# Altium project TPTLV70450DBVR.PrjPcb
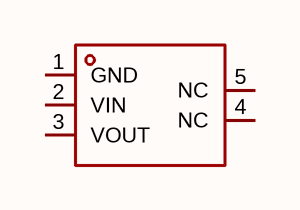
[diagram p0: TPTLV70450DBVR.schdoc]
1 sheet, 1 parts. Net scope: global (net labels, ports and power ports of the same name join across sheets).

## Sheet TPTLV70450DBVR.schdoc
size 127 x 101 mm

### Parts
U?  tptlv70450dbvr  [SOT-23-5_L3.0-W1.6-P0.95-LS2.8-BR]  (value not drawn)

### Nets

Not connected (* = marked no-connect by the designer): U? 1(GND) 2(VIN) 3(VOUT) 4(NC) 5(NC)

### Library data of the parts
U? = tptlv70450dbvr: 输出极性:正极;工作电压:36V;输出电压:5V;输出电流:150mA;电源纹波抑制比(PSRR):68dB;输出类型:固定;; Manufacturer: TECH PUBLIC(台舟); AddInBom: yes; ModelId: 72410e292833493f86746b22636ce101; ModelTransform: 110.236,116.1415,0,0,0,0,0.002,0.001,0; Output Configuration: 正极; Voltage - Supply: 36V; Output Voltage: 5V; Output Current: 150mA; Power Supply Rejection Ratio (PSRR): 68dB; standby current: 2uA; Noise: 120uVrms; Output Type: 固定; Number of Outputs: 1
